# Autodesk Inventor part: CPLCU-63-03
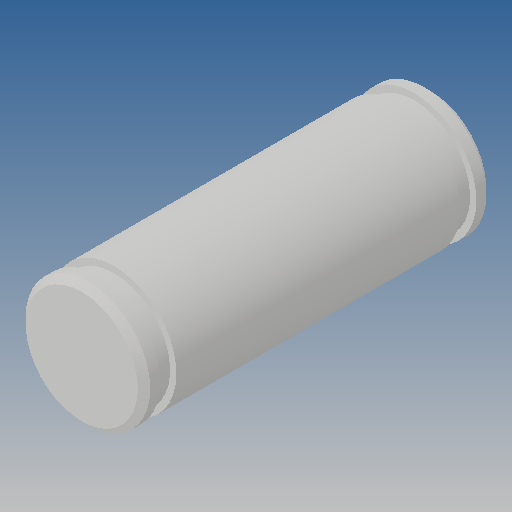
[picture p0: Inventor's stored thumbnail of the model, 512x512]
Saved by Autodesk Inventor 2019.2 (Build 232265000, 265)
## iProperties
Created: 2010-03
Part Number: CPLCU-63-03
Material: Ogólny
Document SubType Name: Modeling
Designer: CADENGINEERING4
Density: 1 g/cm^3
Appearance: Domyślna
Author: CADENGINEERING4
Revision Number: 2LAST_VERSION
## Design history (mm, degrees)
feature "Baza1"
node "Bryła1"
